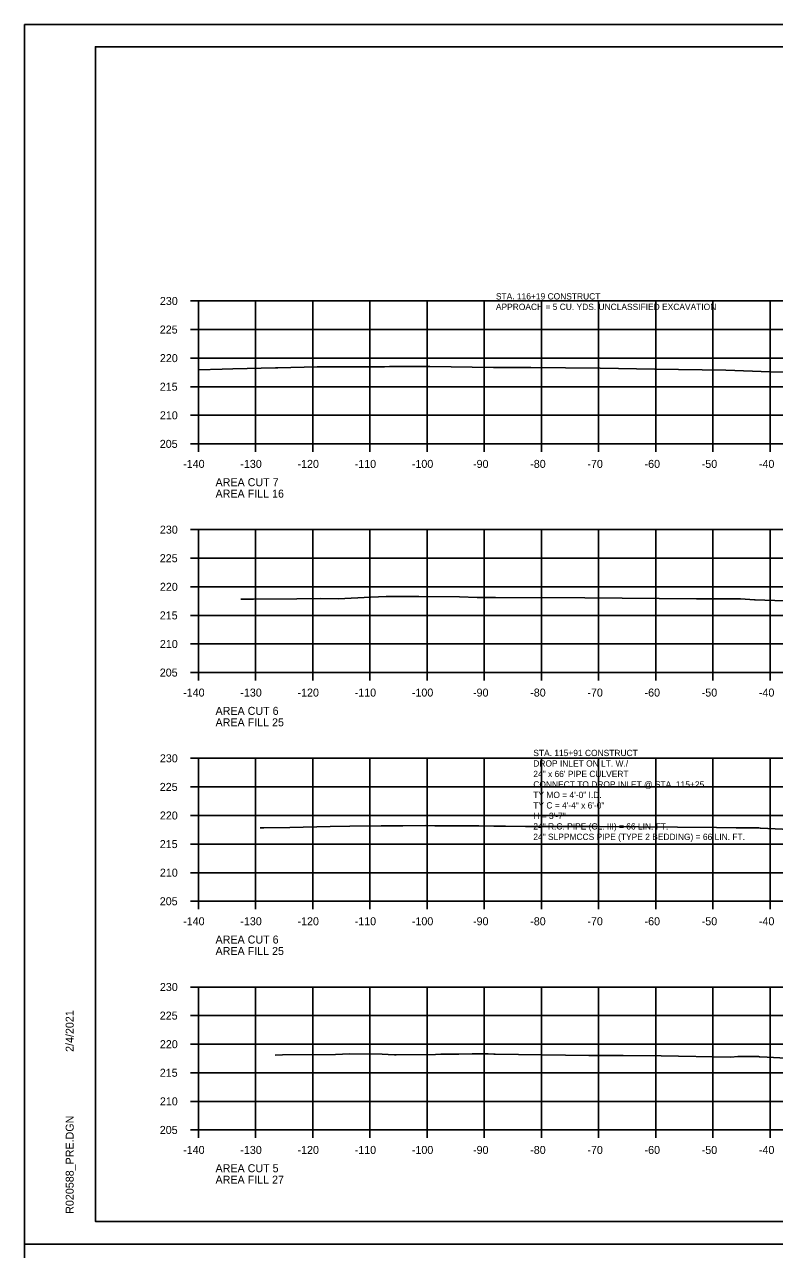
# Model space of a CAD drawing. Extents: x 1368968 to 1369915, y 377395 to 380381.
# Drawn here: x 1369581.4 to 1369712.5, y 378887.1 to 379101.4 of the extents above; entities that cross this region are included whole.
import ezdxf

# ---------------------------------------------------------------- set-up
doc = ezdxf.new("R2010")
doc.units = 0
for name, color, linetype in [('S_BREAKLINE_ANNOT', 7, 'Continuous'), ('S_BRIDGE', 7, 'Continuous'), ('S_BRIDGE_ANNOT', 7, 'Continuous'), ('S_CONTOUR_MINOR', 7, 'Continuous'), ('S_CTL_TABLE', 7, 'Continuous'), ('S_DITCHLINE_ANNOT', 7, 'Continuous'), ('S_DROP_INLET', 7, 'Continuous')]:
    doc.layers.add(name, color=color, linetype=linetype)

msp = doc.modelspace()

# ---------------------------------------------------------------- linework, layer by layer
at = {"layer": 'S_BREAKLINE_ANNOT'}
for p, q in [((1369610.38, 379053.04), (1369611.78, 379053.04)), ((1369611.78, 379028.04), (1369611.78, 379053.04)), ((1369610.38, 379048.04), (1369611.78, 379048.04)), ((1369610.38, 379043.04), (1369611.78, 379043.04)), ((1369610.38, 379038.04), (1369611.78, 379038.04)), ((1369610.38, 379033.04), (1369611.78, 379033.04)), ((1369610.38, 379028.04), (1369611.78, 379028.04)), ((1369611.78, 379028.04), (1369891.78, 379028.04)), ((1369611.78, 379026.64), (1369611.78, 379028.04)), ((1369621.78, 379026.64), (1369621.78, 379028.04)), ((1369631.78, 379026.64), (1369631.78, 379028.04)), ((1369641.78, 379026.64), (1369641.78, 379028.04)), ((1369651.78, 379026.64), (1369651.78, 379028.04)), ((1369661.78, 379026.64), (1369661.78, 379028.04)), ((1369671.78, 379026.64), (1369671.78, 379028.04)), ((1369681.78, 379026.64), (1369681.78, 379028.04)), ((1369691.78, 379026.64), (1369691.78, 379028.04)), ((1369701.78, 379026.64), (1369701.78, 379028.04)), ((1369711.78, 379026.64), (1369711.78, 379028.04)), ((1369610.38, 379013.04), (1369611.78, 379013.04)), ((1369611.78, 378988.04), (1369611.78, 379013.04)), ((1369610.38, 379008.04), (1369611.78, 379008.04)), ((1369610.38, 379003.04), (1369611.78, 379003.04)), ((1369610.38, 378998.04), (1369611.78, 378998.04)), ((1369610.38, 378993.04), (1369611.78, 378993.04)), ((1369610.38, 378988.04), (1369611.78, 378988.04)), ((1369611.78, 378988.04), (1369891.78, 378988.04)), ((1369611.78, 378986.64), (1369611.78, 378988.04)), ((1369621.78, 378986.64), (1369621.78, 378988.04)), ((1369631.78, 378986.64), (1369631.78, 378988.04)), ((1369641.78, 378986.64), (1369641.78, 378988.04)), ((1369651.78, 378986.64), (1369651.78, 378988.04)), ((1369661.78, 378986.64), (1369661.78, 378988.04)), ((1369671.78, 378986.64), (1369671.78, 378988.04)), ((1369681.78, 378986.64), (1369681.78, 378988.04)), ((1369691.78, 378986.64), (1369691.78, 378988.04)), ((1369701.78, 378986.64), (1369701.78, 378988.04)), ((1369711.78, 378986.64), (1369711.78, 378988.04)), ((1369610.38, 378973.04), (1369611.78, 378973.04)), ((1369611.78, 378948.04), (1369611.78, 378973.04)), ((1369610.38, 378968.04), (1369611.78, 378968.04)), ((1369610.38, 378963.04), (1369611.78, 378963.04)), ((1369610.38, 378958.04), (1369611.78, 378958.04)), ((1369610.38, 378953.04), (1369611.78, 378953.04)), ((1369610.38, 378948.04), (1369611.78, 378948.04)), ((1369611.78, 378948.04), (1369891.78, 378948.04)), ((1369611.78, 378946.64), (1369611.78, 378948.04)), ((1369621.78, 378946.64), (1369621.78, 378948.04)), ((1369631.78, 378946.64), (1369631.78, 378948.04)), ((1369641.78, 378946.64), (1369641.78, 378948.04)), ((1369651.78, 378946.64), (1369651.78, 378948.04)), ((1369661.78, 378946.64), (1369661.78, 378948.04)), ((1369671.78, 378946.64), (1369671.78, 378948.04)), ((1369681.78, 378946.64), (1369681.78, 378948.04)), ((1369691.78, 378946.64), (1369691.78, 378948.04)), ((1369701.78, 378946.64), (1369701.78, 378948.04)), ((1369711.78, 378946.64), (1369711.78, 378948.04)), ((1369610.38, 378933.04), (1369611.78, 378933.04)), ((1369611.78, 378908.04), (1369611.78, 378933.04)), ((1369610.38, 378928.04), (1369611.78, 378928.04)), ((1369610.38, 378923.04), (1369611.78, 378923.04)), ((1369610.38, 378918.04), (1369611.78, 378918.04)), ((1369610.38, 378913.04), (1369611.78, 378913.04)), ((1369610.38, 378908.04), (1369611.78, 378908.04)), ((1369611.78, 378908.04), (1369891.78, 378908.04)), ((1369611.78, 378906.64), (1369611.78, 378908.04)), ((1369621.78, 378906.64), (1369621.78, 378908.04)), ((1369631.78, 378906.64), (1369631.78, 378908.04)), ((1369641.78, 378906.64), (1369641.78, 378908.04)), ((1369651.78, 378906.64), (1369651.78, 378908.04)), ((1369661.78, 378906.64), (1369661.78, 378908.04)), ((1369671.78, 378906.64), (1369671.78, 378908.04)), ((1369681.78, 378906.64), (1369681.78, 378908.04)), ((1369691.78, 378906.64), (1369691.78, 378908.04)), ((1369701.78, 378906.64), (1369701.78, 378908.04)), ((1369711.78, 378906.64), (1369711.78, 378908.04))]:
    msp.add_line(p, q, dxfattribs=at)
at = {"layer": 'S_BRIDGE_ANNOT'}
for p, q in [((1369593.78, 379097.5), (1369909.96, 379097.5)), ((1369593.78, 378892.04), (1369593.78, 379097.5)), ((1369593.78, 378892.04), (1369593.78, 378892.04)), ((1369909.96, 378892.04), (1369593.78, 378892.04))]:
    msp.add_line(p, q, dxfattribs=at)
at = {"layer": 'S_CTL_TABLE'}
for points in [[(1369611.78, 379040.97), (1369615.96, 379041.11), (1369617.79, 379041.15), (1369625.26, 379041.32), (1369625.66, 379041.34), (1369632.53, 379041.49), (1369644.36, 379041.53), (1369645.18, 379041.56), (1369652.27, 379041.55), (1369663.39, 379041.43), (1369669.95, 379041.42), (1369682.05, 379041.28), (1369691.61, 379041.11), (1369704.01, 379040.94), (1369711.77, 379040.66), (1369717.2, 379040.51)], [(1369619.18, 379000.89), (1369621.4, 379000.87), (1369628.99, 379000.92), (1369633.12, 379000.98), (1369636.25, 379000.96), (1369641.97, 379001.25), (1369644.63, 379001.34), (1369644.78, 379001.34), (1369645.49, 379001.34), (1369649.76, 379001.32), (1369650.11, 379001.32), (1369650.21, 379001.32), (1369650.34, 379001.32), (1369657.47, 379001.26), (1369660.54, 379001.2), (1369661.18, 379001.2), (1369662.82, 379001.17), (1369663.77, 379001.17), (1369679.39, 379001.11), (1369698.91, 379000.96), (1369704.46, 379000.94), (1369706.59, 379000.91), (1369709.03, 379000.79), (1369709.14, 379000.79), (1369721.19, 379000.34)], [(1369622.57, 378960.89), (1369623.2, 378960.89), (1369627.75, 378960.92), (1369634.84, 378961.14), (1369638.26, 378961.2), (1369643.74, 378961.25), (1369647.55, 378961.26), (1369651.48, 378961.27), (1369653.11, 378961.26), (1369654.58, 378961.25), (1369656.34, 378961.25), (1369659.52, 378961.22), (1369659.64, 378961.22), (1369659.67, 378961.22), (1369660.82, 378961.22), (1369663.48, 378961.18), (1369665.51, 378961.16), (1369668.98, 378961.14), (1369681.91, 378961.09), (1369702.38, 378960.94), (1369705.83, 378960.87), (1369706.16, 378960.91), (1369708.89, 378960.9), (1369709.79, 378960.89), (1369709.83, 378960.87), (1369710.09, 378960.81), (1369719.09, 378960.4)], [(1369625.19, 378921.14), (1369626.49, 378921.16), (1369635.77, 378921.26), (1369638.22, 378921.37), (1369643.91, 378921.27), (1369644.95, 378921.26), (1369646.1, 378921.19), (1369646.4, 378921.17), (1369653.25, 378921.26), (1369654.18, 378921.27), (1369657.35, 378921.3), (1369659.64, 378921.33), (1369661.11, 378921.33), (1369661.67, 378921.33), (1369662.37, 378921.33), (1369662.48, 378921.33), (1369663.44, 378921.32), (1369663.67, 378921.32), (1369680.06, 378921.08), (1369680.72, 378921.08), (1369681.85, 378921.07), (1369686.05, 378921.05), (1369692.71, 378921), (1369704.93, 378920.77), (1369706.13, 378920.91), (1369706.44, 378920.91), (1369709.76, 378920.89), (1369709.92, 378920.8), (1369709.94, 378920.8), (1369711.26, 378920.74), (1369722.37, 378920.16)]]:
    msp.add_lwpolyline(points, dxfattribs=at)
at = {"layer": 'S_DITCHLINE_ANNOT'}
for p, q in [((1369611.78, 379053.04), (1369891.78, 379053.04)), ((1369611.78, 379028.04), (1369611.78, 379053.04)), ((1369621.78, 379028.04), (1369621.78, 379053.04)), ((1369631.78, 379028.04), (1369631.78, 379053.04)), ((1369641.78, 379028.04), (1369641.78, 379053.04)), ((1369651.78, 379028.04), (1369651.78, 379053.04)), ((1369661.78, 379028.04), (1369661.78, 379053.04)), ((1369671.78, 379028.04), (1369671.78, 379053.04)), ((1369681.78, 379028.04), (1369681.78, 379053.04)), ((1369691.78, 379028.04), (1369691.78, 379053.04)), ((1369701.78, 379028.04), (1369701.78, 379053.04)), ((1369711.78, 379028.04), (1369711.78, 379053.04)), ((1369611.78, 379048.04), (1369891.78, 379048.04)), ((1369611.78, 379043.04), (1369891.78, 379043.04)), ((1369611.78, 379038.04), (1369891.78, 379038.04)), ((1369611.78, 379033.04), (1369891.78, 379033.04)), ((1369611.78, 379028.04), (1369891.78, 379028.04)), ((1369611.78, 379013.04), (1369891.78, 379013.04)), ((1369611.78, 378988.04), (1369611.78, 379013.04)), ((1369621.78, 378988.04), (1369621.78, 379013.04)), ((1369631.78, 378988.04), (1369631.78, 379013.04)), ((1369641.78, 378988.04), (1369641.78, 379013.04)), ((1369651.78, 378988.04), (1369651.78, 379013.04)), ((1369661.78, 378988.04), (1369661.78, 379013.04)), ((1369671.78, 378988.04), (1369671.78, 379013.04)), ((1369681.78, 378988.04), (1369681.78, 379013.04)), ((1369691.78, 378988.04), (1369691.78, 379013.04)), ((1369701.78, 378988.04), (1369701.78, 379013.04)), ((1369711.78, 378988.04), (1369711.78, 379013.04)), ((1369611.78, 379008.04), (1369891.78, 379008.04)), ((1369611.78, 379003.04), (1369891.78, 379003.04)), ((1369611.78, 378998.04), (1369891.78, 378998.04)), ((1369611.78, 378993.04), (1369891.78, 378993.04)), ((1369611.78, 378988.04), (1369891.78, 378988.04)), ((1369611.78, 378973.04), (1369891.78, 378973.04)), ((1369611.78, 378948.04), (1369611.78, 378973.04)), ((1369621.78, 378948.04), (1369621.78, 378973.04)), ((1369631.78, 378948.04), (1369631.78, 378973.04)), ((1369641.78, 378948.04), (1369641.78, 378973.04)), ((1369651.78, 378948.04), (1369651.78, 378973.04)), ((1369661.78, 378948.04), (1369661.78, 378973.04)), ((1369671.78, 378948.04), (1369671.78, 378973.04)), ((1369681.78, 378948.04), (1369681.78, 378973.04)), ((1369691.78, 378948.04), (1369691.78, 378973.04)), ((1369701.78, 378948.04), (1369701.78, 378973.04)), ((1369711.78, 378948.04), (1369711.78, 378973.04)), ((1369611.78, 378968.04), (1369891.78, 378968.04)), ((1369611.78, 378963.04), (1369891.78, 378963.04)), ((1369611.78, 378958.04), (1369891.78, 378958.04)), ((1369611.78, 378953.04), (1369891.78, 378953.04)), ((1369611.78, 378948.04), (1369891.78, 378948.04)), ((1369611.78, 378933.04), (1369891.78, 378933.04)), ((1369611.78, 378908.04), (1369611.78, 378933.04)), ((1369621.78, 378908.04), (1369621.78, 378933.04)), ((1369631.78, 378908.04), (1369631.78, 378933.04)), ((1369641.78, 378908.04), (1369641.78, 378933.04)), ((1369651.78, 378908.04), (1369651.78, 378933.04)), ((1369661.78, 378908.04), (1369661.78, 378933.04)), ((1369671.78, 378908.04), (1369671.78, 378933.04)), ((1369681.78, 378908.04), (1369681.78, 378933.04)), ((1369691.78, 378908.04), (1369691.78, 378933.04)), ((1369701.78, 378908.04), (1369701.78, 378933.04)), ((1369711.78, 378908.04), (1369711.78, 378933.04)), ((1369611.78, 378928.04), (1369891.78, 378928.04)), ((1369611.78, 378923.04), (1369891.78, 378923.04)), ((1369611.78, 378918.04), (1369891.78, 378918.04)), ((1369611.78, 378913.04), (1369891.78, 378913.04)), ((1369611.78, 378908.04), (1369891.78, 378908.04))]:
    msp.add_line(p, q, dxfattribs=at)
at = {"layer": 'S_DROP_INLET'}
for p, q in [((1369581.38, 379101.4), (1369914.71, 379101.4)), ((1369581.38, 378888.06), (1369914.71, 378888.06)), ((1369581.38, 378888.06), (1369914.71, 378888.06))]:
    msp.add_line(p, q, dxfattribs=at)
for points in [[(1369581.37, 379101.4), (1369914.71, 379101.4), (1369914.71, 378888.06), (1369581.37, 378888.06)], [(1369827.7, 379097.5), (1369827.7, 379087.62), (1369863.43, 379087.62), (1369863.43, 379084.7), (1369886.63, 379084.7), (1369886.63, 379060.37), (1369909.96, 379060.37), (1369909.96, 378892.04), (1369593.78, 378892.04), (1369593.78, 379097.5)], [(1369581.37, 378888.06), (1369914.71, 378888.06), (1369914.71, 378674.72), (1369581.37, 378674.72)]]:
    msp.add_lwpolyline(points, close=True, dxfattribs=at)

# ---------------------------------------------------------------- texts
at = {"layer": 'S_BRIDGE'}
for s, p in [('230', (1369605.05, 379052.34)), ('225', (1369605.03, 379047.34)), ('220', (1369605.05, 379042.34)), ('215', (1369605.03, 379037.34)), ('210', (1369605.05, 379032.34)), ('205', (1369605.03, 379027.34)), ('-140', (1369609.12, 379023.84)), ('-130', (1369619.12, 379023.84)), ('-120', (1369629.12, 379023.84)), ('-110', (1369639.12, 379023.84)), ('-100', (1369649.12, 379023.84)), ('-90', (1369659.82, 379023.84)), ('-80', (1369669.82, 379023.84)), ('-70', (1369679.82, 379023.84)), ('-60', (1369689.82, 379023.84)), ('-50', (1369699.82, 379023.84)), ('-40', (1369709.82, 379023.84)), ('AREA CUT 7', (1369614.78, 379020.64)), ('AREA FILL 16', (1369614.78, 379018.64)), ('230', (1369605.05, 379012.34)), ('225', (1369605.03, 379007.34)), ('220', (1369605.05, 379002.34)), ('215', (1369605.03, 378997.34)), ('210', (1369605.05, 378992.34)), ('205', (1369605.03, 378987.34)), ('-140', (1369609.12, 378983.84)), ('-130', (1369619.12, 378983.84)), ('-120', (1369629.12, 378983.84)), ('-110', (1369639.12, 378983.84)), ('-100', (1369649.12, 378983.84)), ('-90', (1369659.82, 378983.84)), ('-80', (1369669.82, 378983.84)), ('-70', (1369679.82, 378983.84)), ('-60', (1369689.82, 378983.84)), ('-50', (1369699.82, 378983.84)), ('-40', (1369709.82, 378983.84)), ('AREA CUT 6', (1369614.78, 378980.64)), ('AREA FILL 25', (1369614.78, 378978.64)), ('230', (1369605.05, 378972.34)), ('225', (1369605.03, 378967.34)), ('220', (1369605.05, 378962.34)), ('215', (1369605.03, 378957.34)), ('210', (1369605.05, 378952.34)), ('205', (1369605.03, 378947.34)), ('-140', (1369609.12, 378943.84)), ('-130', (1369619.12, 378943.84)), ('-120', (1369629.12, 378943.84)), ('-110', (1369639.12, 378943.84)), ('-100', (1369649.12, 378943.84)), ('-90', (1369659.82, 378943.84)), ('-80', (1369669.82, 378943.84)), ('-70', (1369679.82, 378943.84)), ('-60', (1369689.82, 378943.84)), ('-50', (1369699.82, 378943.84)), ('-40', (1369709.82, 378943.84)), ('AREA CUT 6', (1369614.78, 378940.64)), ('AREA FILL 25', (1369614.78, 378938.64)), ('230', (1369605.05, 378932.34)), ('225', (1369605.03, 378927.34)), ('220', (1369605.05, 378922.34)), ('215', (1369605.03, 378917.34)), ('210', (1369605.05, 378912.34)), ('205', (1369605.03, 378907.34)), ('-140', (1369609.12, 378903.84)), ('-130', (1369619.12, 378903.84)), ('-120', (1369629.12, 378903.84)), ('-110', (1369639.12, 378903.84)), ('-100', (1369649.12, 378903.84)), ('-90', (1369659.82, 378903.84)), ('-80', (1369669.82, 378903.84)), ('-70', (1369679.82, 378903.84)), ('-60', (1369689.82, 378903.84)), ('-50', (1369699.82, 378903.84)), ('-40', (1369709.82, 378903.84)), ('AREA CUT 5', (1369614.78, 378900.64)), ('AREA FILL 27', (1369614.78, 378898.64))]:
    msp.add_text(s, height=1.4, dxfattribs=at).set_placement(p)
at = {"layer": 'S_BRIDGE_ANNOT'}
for s, p in [('2/4/2021', (1369589.97, 378921.69)), ('R020588_PRE.DGN', (1369589.97, 378893.37))]:
    msp.add_text(s, height=1.4, rotation=90, dxfattribs=at).set_placement(p)
at = {"layer": 'S_CONTOUR_MINOR'}
for s, p in [('STA. 116+19 CONSTRUCT ', (1369663.82, 379053.3)), ('APPROACH = 5 CU. YDS. UNCLASSIFIED EXCAVATION', (1369663.82, 379051.46)), ('STA. 115+91 CONSTRUCT', (1369670.36, 378973.43)), ('DROP INLET ON LT. W./', (1369670.36, 378971.59)), ('24" x 66\' PIPE CULVERT', (1369670.36, 378969.76)), ('CONNECT TO DROP INLET @ STA. 115+25', (1369670.36, 378967.93)), ('TY MO = 4\'-0" I.D.', (1369670.36, 378966.09)), ('TY C = 4\'-4" x 6\'-0"', (1369670.36, 378964.26)), ('H = 3\'-7"', (1369670.36, 378962.43)), ('24" R.C. PIPE (CL. III) = 66 LIN. FT.', (1369670.36, 378960.59)), ('24" SLPPMCCS PIPE (TYPE 2 BEDDING) = 66 LIN. FT.', (1369670.36, 378958.76))]:
    msp.add_text(s, height=1.1, dxfattribs=at).set_placement(p)

doc.saveas('drawing.dxf')
